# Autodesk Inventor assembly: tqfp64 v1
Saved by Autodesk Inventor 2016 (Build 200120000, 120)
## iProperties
Created: 2016-09
Part Number: tqfp64 v1
Document SubType Name: Assembly
Designer: Administrator
Author: Administrator
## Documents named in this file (3)
- c:\worker\convert-fusion-aug-2016\tmp\job-1\13\output\files\2055b865-881d-4af8-ae30-e7b46ec3c804\tqfp64 v1.iam
- c:\worker\convert-fusion-aug-2016\tmp\job-1\13\output\files\2055b865-881d-4af8-ae30-e7b46ec3c804\package (1).ipt
- c:\worker\convert-fusion-aug-2016\tmp\job-1\13\output\files\2055b865-881d-4af8-ae30-e7b46ec3c804\lead (3).ipt
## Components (65 placed, 2 different names)
1. package (1):1
2. lead (3):1
3. lead (3):191
4. lead (3):192
5. lead (3):193
6. lead (3):194
7. lead (3):195
8. lead (3):196
9. lead (3):197
10. lead (3):198
11. lead (3):199
12. lead (3):200
13. lead (3):201
14. lead (3):202
15. lead (3):203
16. lead (3):204
17. lead (3):205
18. lead (3):212
19. lead (3):213
20. lead (3):214
21. lead (3):221
22. lead (3):206
23. lead (3):215
24. lead (3):216
25. lead (3):218
26. lead (3):219
27. lead (3):211
28. lead (3):208
29. lead (3):207
30. lead (3):210
31. lead (3):209
32. lead (3):220
33. lead (3):217
34. lead (3):236
35. lead (3):237
36. lead (3):226
37. lead (3):235
38. lead (3):230
39. lead (3):227
40. lead (3):228
41. lead (3):232
42. lead (3):233
43. lead (3):225
44. lead (3):222
45. lead (3):231
46. lead (3):224
47. lead (3):223
48. lead (3):234
49. lead (3):229
50. lead (3):242
51. lead (3):249
52. lead (3):250
53. lead (3):241
54. lead (3):243
55. lead (3):251
56. lead (3):252
57. lead (3):238
58. lead (3):239
59. lead (3):248
60. lead (3):245
61. lead (3):244
62. lead (3):247
63. lead (3):246
64. lead (3):240
65. lead (3):253
